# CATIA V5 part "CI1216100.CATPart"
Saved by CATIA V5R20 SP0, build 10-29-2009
Part number: CI1216100
Bounding box of the stored display mesh (mm): x -15 to 15, y -11.764 to 124, z -17.351 to 17.399
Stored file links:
  C:\Users\Raffaele\Desktop\3D X SITO CF\BOLEX\19-INCLINED ASSEMBLY REF_CI\CI1216100.CATPart

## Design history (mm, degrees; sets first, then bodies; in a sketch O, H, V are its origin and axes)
Set1
  DatumSurface1 to DatumSurface16 "MANIFOLD_SOLID_BREP #385"
  DatumSurface17 to DatumSurface39 "MANIFOLD_SOLID_BREP #1110"
Body1 (main body)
